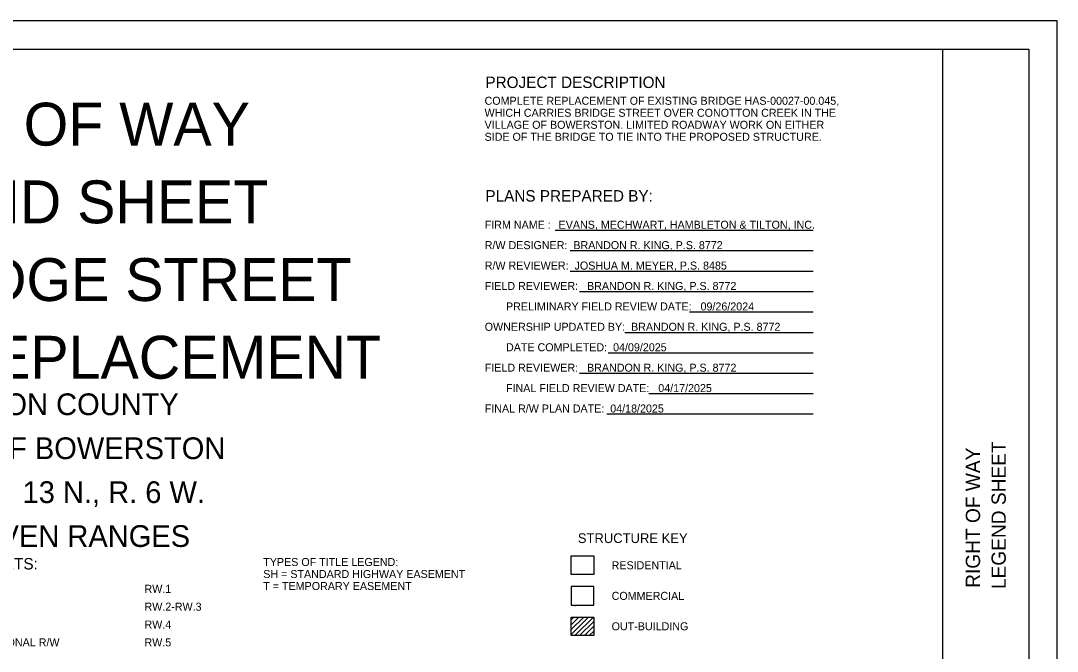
# Model space of a CAD drawing. Extents: x 0 to 34, y 0 to 22.
# Drawn here: x 15.87 to 34, y 10.97 to 22 of the extents above; entities that cross this region are included whole.
import ezdxf

# ---------------------------------------------------------------- set-up
doc = ezdxf.new("R2010")
doc.units = 0
for name, color, linetype in [('SC_Shading1', 7, 'Continuous'), ('SH_Border', 7, 'Continuous'), ('SH_Cut_Line', 7, 'Continuous'), ('SH_Data', 7, 'Continuous'), ('SH_Text', 7, 'Continuous')]:
    doc.layers.add(name, color=color, linetype=linetype)

msp = doc.modelspace()

# ---------------------------------------------------------------- linework, layer by layer
at = {"layer": 'SC_Shading1'}
msp.add_lwpolyline([(25.498, 11.781), (25.896, 11.781), (25.896, 12.107), (25.498, 12.107)], close=True, dxfattribs=at)
at = {"layer": 'SH_Border'}
msp.add_line((32, 0.5), (32, 21.5), dxfattribs=at)
msp.add_lwpolyline([(1.5, 21.5), (33.5, 21.5), (33.5, 0.5), (1.5, 0.5)], close=True, dxfattribs=at)
at = {"layer": 'SH_Cut_Line'}
msp.add_lwpolyline([(0, 0), (34, 0), (34, 22), (0, 22)], close=True, dxfattribs=at)
at = {"layer": 'SH_Text'}
for p, q in [((25.22, 18.336), (29.734, 18.336)), ((25.484, 17.979), (29.734, 17.979)), ((25.484, 17.622), (29.734, 17.622)), ((25.648, 17.265), (29.734, 17.265)), ((27.567, 16.907), (29.734, 16.907)), ((26.439, 16.55), (29.734, 16.55)), ((26.149, 16.193), (29.734, 16.193)), ((25.648, 15.836), (29.734, 15.836)), ((26.86, 15.479), (29.734, 15.479)), ((26.122, 15.122), (29.734, 15.122)), ((25.568, 11.763), (25.569, 11.764)), ((25.498, 11.52), (25.55, 11.571)), ((25.498, 11.435), (25.635, 11.571)), ((25.498, 11.351), (25.719, 11.571)), ((25.498, 11.266), (25.804, 11.571)), ((25.563, 11.245), (25.889, 11.571)), ((25.568, 11.443), (25.572, 11.438)), ((25.648, 11.245), (25.896, 11.493)), ((25.732, 11.245), (25.896, 11.409)), ((25.817, 11.245), (25.896, 11.324))]:
    msp.add_line(p, q, dxfattribs=at)
for points in [[(25.498, 12.642), (25.896, 12.642), (25.896, 12.316), (25.498, 12.316)], [(25.498, 11.571), (25.896, 11.571), (25.896, 11.245), (25.498, 11.245)]]:
    msp.add_lwpolyline(points, close=True, dxfattribs=at)

# ---------------------------------------------------------------- texts
at = {"layer": 'SH_Data'}
for s, height, p in [('RIGHT OF WAY', 0.75, (12.527, 19.816)), ('LEGEND SHEET', 0.75, (12.458, 18.457)), ('HAS-BRIDGE STREET', 0.75, (11.182, 17.098)), ('BRIDGE REPLACEMENT', 0.75, (10.526, 15.739)), ('HARRISON COUNTY', 0.38, (13.669, 15.102)), ('VILLAGE OF BOWERSTON', 0.38, (13.014, 14.333)), ('SEC. 27, T. 13 N., R. 6 W.', 0.38, (13.138, 13.565)), ('OLD SEVEN RANGES', 0.38, (13.64, 12.797)), ('INDEX OF SHEETS:', 0.2, (13.692, 12.403)), ('RW.1', 0.14, (18.038, 11.994)), ('RW.2-RW.3', 0.14, (18.038, 11.682)), ('RW.4', 0.14, (18.038, 11.37)), ('SUMMARY OF ADDITIONAL R/W', 0.14, (13.692, 11.058)), ('RW.5', 0.14, (18.038, 11.058))]:
    msp.add_text(s, height=height, dxfattribs=at).set_placement(p)
for s, p in [('RIGHT OF WAY', (32.65, 12.082)), ('LEGEND SHEET', (33.1, 12.06))]:
    msp.add_text(s, height=0.25, rotation=90, dxfattribs=at).set_placement(p)
at = {"layer": 'SH_Text'}
for s, height, p in [('PROJECT DESCRIPTION', 0.2, (24, 20.823)), ('COMPLETE REPLACEMENT OF EXISTING BRIDGE HAS-00027-00.045, ', 0.14, (23.985, 20.53)), ('WHICH CARRIES BRIDGE STREET OVER CONOTTON CREEK IN THE ', 0.14, (23.985, 20.32)), ('VILLAGE OF BOWERSTON. LIMITED ROADWAY WORK ON EITHER ', 0.14, (23.985, 20.11)), ('SIDE OF THE BRIDGE TO TIE INTO THE PROPOSED STRUCTURE.', 0.14, (23.985, 19.9)), ('PLANS PREPARED BY:', 0.2, (24, 18.837)), ('FIRM NAME : ', 0.14, (23.988, 18.362)), (' EVANS, MECHWART, HAMBLETON & TILTON, INC.', 0.14, (25.228, 18.362)), ('R/W DESIGNER:  BRANDON R. KING, P.S. 8772', 0.14, (23.988, 18.005)), ('R/W REVIEWER:  JOSHUA M. MEYER, P.S. 8485', 0.14, (23.988, 17.648)), ('FIELD REVIEWER:   BRANDON R. KING, P.S. 8772', 0.14, (23.988, 17.291)), ('PRELIMINARY FIELD REVIEW DATE:   09/26/2024', 0.14, (24.36, 16.933)), ('OWNERSHIP UPDATED BY:  BRANDON R. KING, P.S. 8772', 0.14, (23.988, 16.577)), ('DATE COMPLETED:  04/09/2025', 0.14, (24.36, 16.219)), ('FIELD REVIEWER:   BRANDON R. KING, P.S. 8772', 0.14, (23.988, 15.862)), ('FINAL FIELD REVIEW DATE:   04/17/2025', 0.14, (24.36, 15.505)), ('FINAL R/W PLAN DATE:  04/18/2025', 0.14, (23.988, 15.148)), ('STRUCTURE KEY', 0.17, (25.616, 12.865)), ('TYPES OF TITLE LEGEND:', 0.14, (20.115, 12.463)), ('RESIDENTIAL', 0.14, (26.207, 12.406)), ('SH = STANDARD HIGHWAY EASEMENT', 0.14, (20.115, 12.253)), ('T = TEMPORARY EASEMENT', 0.14, (20.115, 12.043)), ('COMMERCIAL', 0.14, (26.207, 11.871)), ('OUT-BUILDING', 0.14, (26.207, 11.339))]:
    msp.add_text(s, height=height, dxfattribs=at).set_placement(p)

doc.saveas('drawing.dxf')
